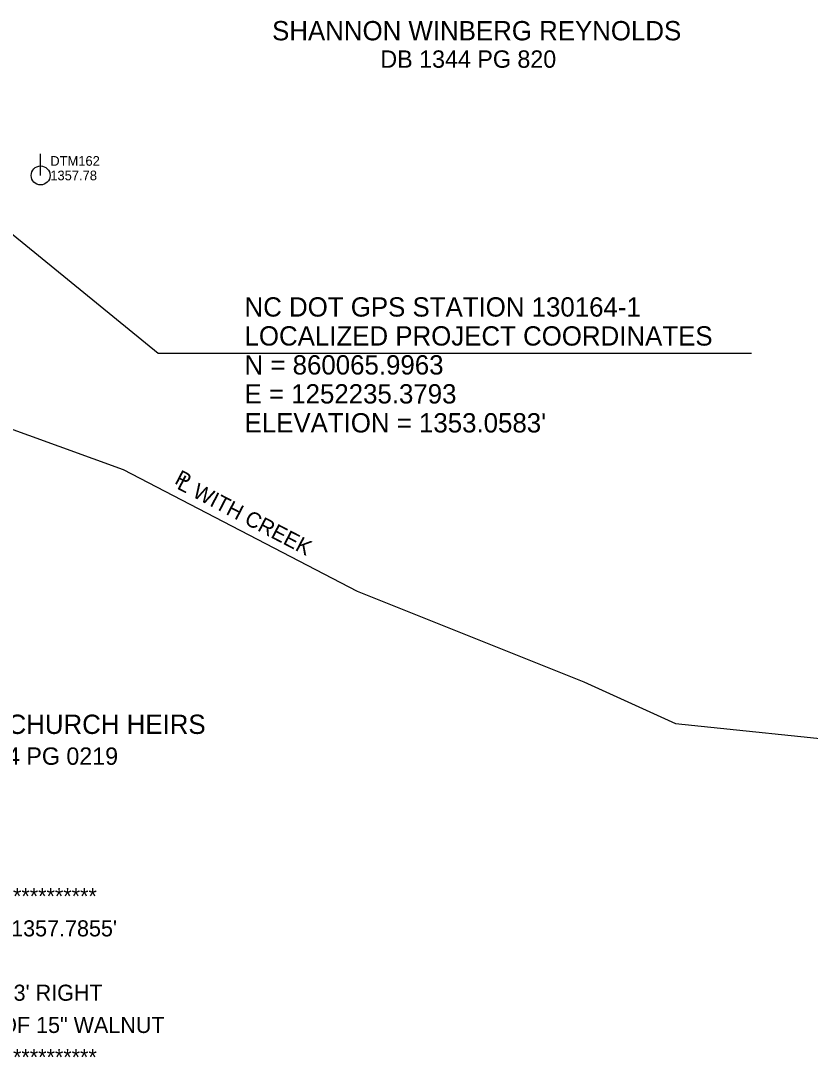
# Model space of a CAD drawing. Extents: x 1251492 to 1253015, y 859607 to 860610.
# Drawn here: x 1252253.4 to 1252457.7, y 859840.1 to 860108.4 of the extents above; entities that cross this region are included whole.
import ezdxf

# ---------------------------------------------------------------- set-up
doc = ezdxf.new("R2010")
doc.units = 0
for name, color, linetype in [('CTL GPS Vertical Text', 7, 'Continuous'), ('CTL Sheet Text', 7, 'Continuous'), ('Default', 7, 'Continuous'), ('Exist Property Deed Book Text', 7, 'Continuous'), ('Exist Property Line', 7, 'Continuous'), ('Exist Property Line Text', 7, 'Continuous'), ('Exist Property Owner Text', 7, 'Continuous'), ('Exist Utilities Power Pole CELL', 7, 'Continuous'), ('Exist Utilities Power Pole Cogo Elevation', 7, 'Continuous'), ('Exist Utilities Power Pole Cogo Number', 7, 'Continuous')]:
    doc.layers.add(name, color=color, linetype=linetype)

msp = doc.modelspace()

# ---------------------------------------------------------------- linework, layer by layer
at = {"layer": 'Default'}
msp.add_lwpolyline([(1252235.38, 860066), (1252289.03, 860022.33), (1252442.5, 860022.33)], dxfattribs=at)
at = {"layer": 'Exist Property Line'}
msp.add_lwpolyline([(1252222.96, 860012.9), (1252279.97, 859992.24), (1252340.48, 859960.73), (1252399.13, 859937.26), (1252422.88, 859926.5), (1252471.07, 859921.5), (1252521.39, 859919.34), (1252547.01, 859914.09), (1252569.55, 859902.66), (1252604.74, 859894.01), (1252643.03, 859888.76), (1252670.15, 859885.63)], dxfattribs=at)
at = {"layer": 'Exist Utilities Power Pole CELL'}
for q in [(1252258.57, 860074), (1252258.57, 860068.37)]:
    msp.add_line((1252258.57, 860068.37), q, dxfattribs=at)
msp.add_circle((1252258.57, 860068.37), 2.45, dxfattribs=at)

# ---------------------------------------------------------------- texts
at = {"layer": 'CTL GPS Vertical Text'}
for s, p in [('NC DOT GPS STATION 130164-1', (1252311.34, 860031.83)), ('LOCALIZED PROJECT COORDINATES', (1252311.34, 860024.33)), ('N = 860065.9963', (1252311.34, 860016.83)), ('E = 1252235.3793', (1252311.34, 860009.33)), ("ELEVATION = 1353.0583'", (1252311.34, 860001.83))]:
    msp.add_text(s, height=5, rotation=359.9944, dxfattribs=at).set_placement(p)
at = {"layer": 'CTL Sheet Text'}
for s, p in [('****************************************', (1252186.38, 859879.69)), ("BM #1       ELEVATION = 1357.7855'", (1252186.38, 859871.35)), ("EL STATION 11+61.00   63' RIGHT", (1252186.38, 859854.69)), ('8" SPIKE SET IN ROOT OF 15" WALNUT', (1252186.38, 859846.35)), ('****************************************', (1252186.38, 859838.02))]:
    msp.add_text(s, height=4.1667, dxfattribs=at).set_placement(p)
at = {"layer": 'Exist Property Deed Book Text'}
for s, p in [('DB 1344 PG 820', (1252346.49, 860096.25)), ('DB 304 PG 0219', (1252233.13, 859915.78))]:
    msp.add_text(s, height=4.5, dxfattribs=at).set_placement(p)
at = {"layer": 'Exist Property Line'}
msp.add_text(' SHANNON WINBERG REYNOLDS', height=5, dxfattribs=at).set_placement((1252316.61, 860103.35))
at = {"layer": 'Exist Property Line Text'}
for s, p in [('P', (1252292.99, 859988.74)), ('L WITH CREEK', (1252293.63, 859987.38))]:
    msp.add_text(s, height=4, rotation=332.4953, dxfattribs=at).set_placement(p)
at = {"layer": 'Exist Property Owner Text'}
msp.add_text('FRANCES CHURCH HEIRS', height=5, dxfattribs=at).set_placement((1252216.2, 859923.77))
at = {"layer": 'Exist Utilities Power Pole Cogo Elevation'}
msp.add_text('1357.78', height=2.5, dxfattribs=at).set_placement((1252261.07, 860067.12))
at = {"layer": 'Exist Utilities Power Pole Cogo Number'}
msp.add_text('DTM162', height=2.5, dxfattribs=at).set_placement((1252261.07, 860070.88))

doc.saveas('drawing.dxf')
